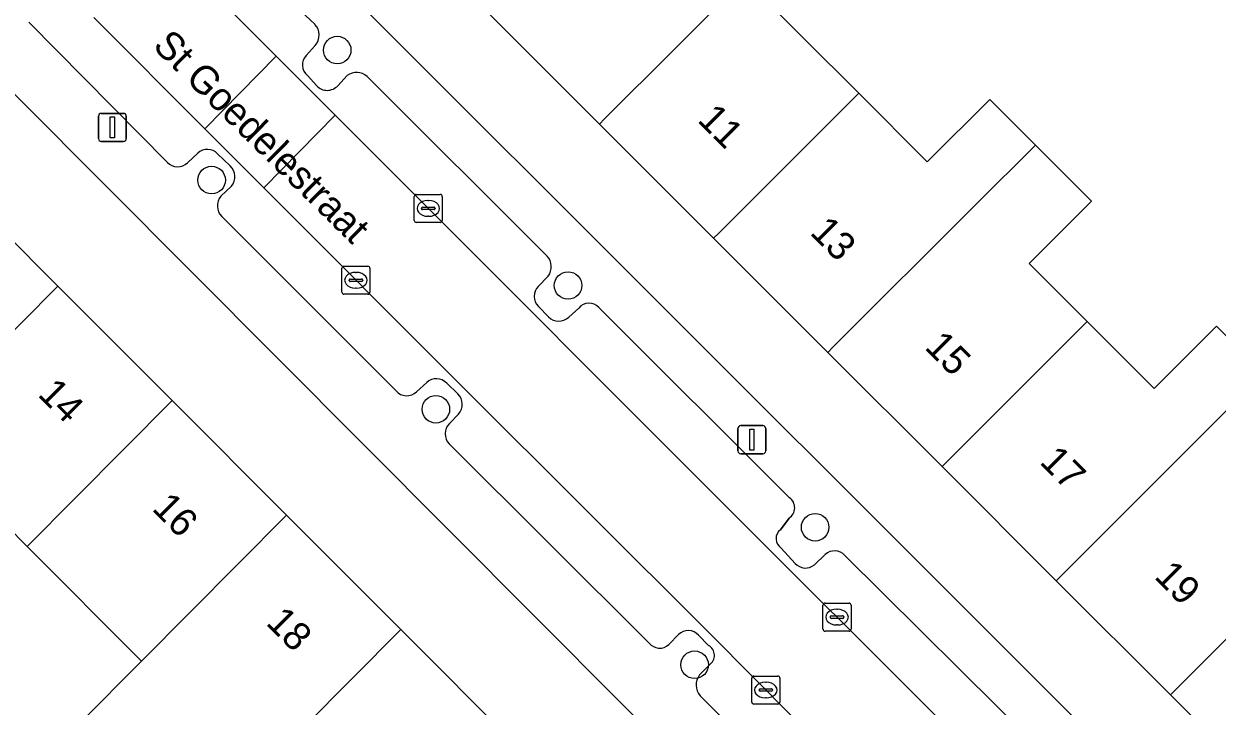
# Model space of a CAD drawing. Extents: x 162523 to 163266, y 381230 to 382050.
# Drawn here: x 162879.64 to 162922.11, y 381652.26 to 381676.55 of the extents above; entities that cross this region are included whole.
import ezdxf

# ---------------------------------------------------------------- set-up
doc = ezdxf.new("R2010")
doc.units = 0
for name, color, linetype in [('IMGEO_Boom', 7, 'Continuous'), ('IMGEO_Erf', 7, 'Continuous'), ('IMGEO_Kolk', 7, 'Continuous'), ('IMGEO_Lichtmast', 7, 'Continuous'), ('IMGEO_Openbare_ruimte_label', 7, 'Continuous'), ('IMGEO_Pand', 7, 'Continuous'), ('IMGEO_Pand_nummerreeks', 7, 'Continuous'), ('IMGEO_Parkeervlak_open', 7, 'Continuous'), ('IMGEO_Rijbaan_lokaal_open', 7, 'Continuous'), ('IMGEO_Voetpad_open', 7, 'Continuous')]:
    doc.layers.add(name, color=color, linetype=linetype)

msp = doc.modelspace()

# ---------------------------------------------------------------- linework, layer by layer
at = {"layer": 'IMGEO_Boom'}
for centre in [(162890.791, 381675.616), (162886.32, 381670.989), (162899.006, 381667.232), (162894.302, 381662.825), (162907.8, 381658.624), (162903.512, 381653.732)]:
    msp.add_circle(centre, 0.489, dxfattribs=at)
at = {"layer": 'IMGEO_Erf'}
for points in [[(162881.716, 381687.133), (162922.581, 381646.284), (162924.703, 381648.404), (162920.45, 381652.657), (162920.379, 381652.728), (162916.456, 381656.651), (162916.385, 381656.722), (162916.314, 381656.793), (162912.391, 381660.716), (162912.32, 381660.787), (162912.249, 381660.858), (162908.326, 381664.781), (162908.255, 381664.852), (162908.184, 381664.923), (162904.26, 381668.847), (162904.189, 381668.918), (162904.118, 381668.989), (162900.195, 381672.912), (162900.124, 381672.983), (162900.053, 381673.054), (162896.13, 381676.977)], [(162905.385, 381678.046), (162909.353, 381674.077), (162911.792, 381671.638), (162914.014, 381673.858), (162915.64, 381672.232), (162915.711, 381672.161), (162917.64, 381670.232), (162915.418, 381668.012), (162917.484, 381665.947), (162919.867, 381663.564), (162920.263, 381663.959), (162922.089, 381665.783), (162923.771, 381664.101)], [(162876.85, 381671.218), (162880.849, 381667.213), (162884.919, 381663.137), (162888.988, 381659.061), (162893.058, 381654.985), (162897.128, 381650.909), (162901.196, 381646.834), (162905.267, 381642.757), (162909.336, 381638.682), (162911.284, 381640.643), (162915.574, 381636.334), (162916.21, 381636.979), (162879.464, 381673.885)], [(162881.631, 381651.654), (162883.818, 381653.856), (162879.758, 381657.941), (162877.555, 381660.157)]]:
    msp.add_lwpolyline(points, dxfattribs=at)
at = {"layer": 'IMGEO_Kolk'}
for p, q in [((162893.605, 381670.477), (162894.457, 381670.477)), ((162893.53, 381669.551), (162893.53, 381670.403)), ((162893.832, 381670.02), (162894.23, 381670.02)), ((162894.018, 381670.257), (162894.043, 381670.257)), ((162894.531, 381670.403), (162894.531, 381669.551)), ((162893.789, 381669.971), (162893.789, 381669.983)), ((162894.227, 381669.934), (162893.829, 381669.934)), ((162894.041, 381669.697), (162894.016, 381669.697)), ((162894.273, 381669.983), (162894.273, 381669.971)), ((162894.457, 381669.477), (162893.605, 381669.477)), ((162891.03, 381667.921), (162891.882, 381667.921)), ((162890.955, 381666.995), (162890.955, 381667.847)), ((162891.257, 381667.464), (162891.655, 381667.464)), ((162891.443, 381667.701), (162891.468, 381667.701)), ((162891.956, 381667.847), (162891.956, 381666.995)), ((162891.214, 381667.415), (162891.214, 381667.427)), ((162891.652, 381667.378), (162891.254, 381667.378)), ((162891.466, 381667.141), (162891.441, 381667.141)), ((162891.698, 381667.427), (162891.698, 381667.415)), ((162891.882, 381666.921), (162891.03, 381666.921)), ((162908.081, 381655), (162908.081, 381655.852)), ((162908.156, 381655.926), (162909.008, 381655.926)), ((162908.569, 381655.706), (162908.594, 381655.706)), ((162909.082, 381655.852), (162909.082, 381655)), ((162908.34, 381655.42), (162908.34, 381655.432)), ((162908.778, 381655.383), (162908.38, 381655.383)), ((162908.383, 381655.469), (162908.781, 381655.469)), ((162908.592, 381655.146), (162908.567, 381655.146)), ((162908.824, 381655.432), (162908.824, 381655.42)), ((162909.008, 381654.926), (162908.156, 381654.926)), ((162905.545, 381652.404), (162905.545, 381653.256)), ((162905.62, 381653.33), (162906.472, 381653.33)), ((162906.033, 381653.11), (162906.058, 381653.11)), ((162906.546, 381653.256), (162906.546, 381652.404)), ((162905.804, 381652.824), (162905.804, 381652.836)), ((162906.242, 381652.787), (162905.844, 381652.787)), ((162905.847, 381652.873), (162906.245, 381652.873)), ((162906.288, 381652.836), (162906.288, 381652.824)), ((162906.472, 381652.33), (162905.62, 381652.33)), ((162906.056, 381652.55), (162906.031, 381652.55))]:
    msp.add_line(p, q, dxfattribs=at)
for points in [[(162893.605, 381670.477), (162894.457, 381670.477)], [(162893.53, 381669.551), (162893.53, 381670.403)], [(162894.531, 381670.403), (162894.531, 381669.551)], [(162894.457, 381669.477), (162893.605, 381669.477)], [(162891.03, 381667.921), (162891.882, 381667.921)], [(162890.955, 381666.995), (162890.955, 381667.847)], [(162891.956, 381667.847), (162891.956, 381666.995)], [(162891.882, 381666.921), (162891.03, 381666.921)], [(162908.081, 381655), (162908.081, 381655.852)], [(162908.156, 381655.926), (162909.008, 381655.926)], [(162909.082, 381655.852), (162909.082, 381655)], [(162909.008, 381654.926), (162908.156, 381654.926)], [(162905.545, 381652.404), (162905.545, 381653.256)], [(162905.62, 381653.33), (162906.472, 381653.33)], [(162906.546, 381653.256), (162906.546, 381652.404)], [(162906.472, 381652.33), (162905.62, 381652.33)]]:
    msp.add_lwpolyline(points, dxfattribs=at)
for centre, radius, start, end in [((162893.607, 381670.401), 0.0765, 91.552, 178.448), ((162893.607, 381670.401), 0.0765, 91.552, 178.448), ((162894.455, 381670.401), 0.0765, 1.552, 88.448), ((162894.455, 381670.401), 0.0765, 1.552, 88.448), ((162893.829, 381669.98), 0.0403, 85.8775, 175.7526), ((162894.234, 381669.982), 0.0386, 1.7309, 96.639), ((162893.826, 381669.97), 0.0366, 178.938, 274.7102), ((162894.23, 381669.977), 0.043, 264.8664, 352.4533), ((162893.607, 381669.553), 0.0765, 181.552, 268.448), ((162893.607, 381669.553), 0.0765, 181.552, 268.448), ((162894.455, 381669.553), 0.0765, 271.552, 358.448), ((162894.455, 381669.553), 0.0765, 271.552, 358.448), ((162891.032, 381667.845), 0.0765, 91.552, 178.448), ((162891.032, 381667.845), 0.0765, 91.552, 178.448), ((162891.88, 381667.845), 0.0765, 1.552, 88.448), ((162891.88, 381667.845), 0.0765, 1.552, 88.448), ((162891.254, 381667.424), 0.0403, 85.8775, 175.7526), ((162891.659, 381667.426), 0.0386, 1.7309, 96.639), ((162891.251, 381667.414), 0.0366, 178.938, 274.7102), ((162891.655, 381667.421), 0.043, 264.8664, 352.4533), ((162891.032, 381666.997), 0.0765, 181.552, 268.448), ((162891.032, 381666.997), 0.0765, 181.552, 268.448), ((162891.88, 381666.997), 0.0765, 271.552, 358.448), ((162891.88, 381666.997), 0.0765, 271.552, 358.448), ((162908.158, 381655.85), 0.0765, 91.552, 178.448), ((162908.158, 381655.85), 0.0765, 91.552, 178.448), ((162909.006, 381655.85), 0.0765, 1.552, 88.448), ((162909.006, 381655.85), 0.0765, 1.552, 88.448), ((162908.38, 381655.429), 0.0403, 85.8775, 175.7526), ((162908.377, 381655.419), 0.0366, 178.938, 274.7102), ((162908.781, 381655.426), 0.043, 264.8664, 352.4533), ((162908.785, 381655.431), 0.0386, 1.7309, 96.639), ((162908.158, 381655.002), 0.0765, 181.552, 268.448), ((162908.158, 381655.002), 0.0765, 181.552, 268.448), ((162909.006, 381655.002), 0.0765, 271.552, 358.448), ((162909.006, 381655.002), 0.0765, 271.552, 358.448), ((162905.622, 381653.254), 0.0765, 91.552, 178.448), ((162905.622, 381653.254), 0.0765, 91.552, 178.448), ((162906.47, 381653.254), 0.0765, 1.552, 88.448), ((162906.47, 381653.254), 0.0765, 1.552, 88.448), ((162905.844, 381652.833), 0.0403, 85.8775, 175.7526), ((162905.841, 381652.823), 0.0366, 178.938, 274.7102), ((162906.245, 381652.83), 0.043, 264.8664, 352.4533), ((162906.249, 381652.835), 0.0386, 1.7309, 96.639), ((162905.622, 381652.406), 0.0765, 181.552, 268.448), ((162905.622, 381652.406), 0.0765, 181.552, 268.448), ((162906.47, 381652.406), 0.0765, 271.552, 358.448), ((162906.47, 381652.406), 0.0765, 271.552, 358.448)]:
    msp.add_arc(centre, radius, start, end, dxfattribs=at)
for centre, major_axis, ratio, start_param, end_param in [((162894.017, 381669.977), (-0.387, 0.002), 0.722429, 4.712389, 7.853982), ((162894.042, 381669.977), (-0.39, 0.002), 0.717154, 1.570796, 4.712389), ((162891.442, 381667.421), (-0.387, 0.002), 0.722429, 4.712389, 7.853982), ((162891.467, 381667.421), (-0.39, 0.002), 0.717154, 1.570796, 4.712389), ((162908.568, 381655.426), (-0.387, 0.002), 0.722429, 4.712389, 7.853982), ((162908.593, 381655.426), (-0.39, 0.002), 0.717154, 1.570796, 4.712389), ((162906.032, 381652.83), (-0.387, 0.002), 0.722429, 4.712389, 7.853982), ((162906.057, 381652.83), (-0.39, 0.002), 0.717154, 1.570796, 4.712389)]:
    msp.add_ellipse(centre, major_axis=major_axis, ratio=ratio, start_param=start_param, end_param=end_param, dxfattribs=at)
at = {"layer": 'IMGEO_Lichtmast'}
for p, q in [((162882.292, 381672.462), (162882.292, 381673.262)), ((162882.292, 381673.262), (162882.292, 381672.462)), ((162882.392, 381673.362), (162883.182, 381673.362)), ((162883.182, 381673.362), (162882.392, 381673.362)), ((162883.282, 381673.262), (162883.282, 381672.462)), ((162883.282, 381672.462), (162883.282, 381673.262)), ((162883.182, 381672.362), (162882.392, 381672.362)), ((162882.392, 381672.362), (162883.182, 381672.362)), ((162905.053, 381661.343), (162905.053, 381662.143)), ((162905.053, 381662.143), (162905.053, 381661.343)), ((162905.153, 381662.243), (162905.943, 381662.243)), ((162905.943, 381662.243), (162905.153, 381662.243)), ((162906.043, 381662.143), (162906.043, 381661.343)), ((162906.043, 381661.343), (162906.043, 381662.143)), ((162905.943, 381661.243), (162905.153, 381661.243)), ((162905.153, 381661.243), (162905.943, 381661.243))]:
    msp.add_line(p, q, dxfattribs=at)
for points in [[(162882.712, 381673.237), (162882.862, 381673.237), (162882.862, 381672.487), (162882.712, 381672.487), (162882.712, 381673.237)], [(162905.473, 381662.118), (162905.623, 381662.118), (162905.623, 381661.368), (162905.473, 381661.368), (162905.473, 381662.118)]]:
    msp.add_lwpolyline(points, dxfattribs=at)
for centre, start, end in [((162882.392, 381673.262), 90, 180), ((162882.392, 381673.262), 90, 180), ((162883.182, 381673.262), 0, 90), ((162883.182, 381673.262), 360, 90), ((162882.392, 381672.462), 180, 270), ((162882.392, 381672.462), 180, 270), ((162883.182, 381672.462), 270, 0), ((162883.182, 381672.462), 270, 0), ((162905.153, 381662.143), 90, 180), ((162905.153, 381662.143), 90, 180), ((162905.943, 381662.143), 0, 90), ((162905.943, 381662.143), 360, 90), ((162905.153, 381661.343), 180, 270), ((162905.153, 381661.343), 180, 270), ((162905.943, 381661.343), 270, 0), ((162905.943, 381661.343), 270, 0)]:
    msp.add_arc(centre, 0.1, start, end, dxfattribs=at)
at = {"layer": 'IMGEO_Pand'}
for points in [[(162907.509, 381680.362), (162905.804, 381682.067), (162904.148, 381680.413), (162903.582, 381679.848), (162901.222, 381682.207), (162896.245, 381677.234), (162896.059, 381677.048), (162896.13, 381676.977), (162900.053, 381673.054), (162900.124, 381672.983), (162900.309, 381673.167), (162905.288, 381678.143), (162905.375, 381678.23)], [(162905.385, 381678.046), (162905.288, 381678.143), (162900.309, 381673.167), (162900.124, 381672.983), (162900.195, 381672.912), (162904.118, 381668.989), (162904.189, 381668.918), (162904.372, 381669.1), (162909.353, 381674.077)], [(162908.255, 381664.852), (162908.436, 381665.033), (162913.502, 381670.096), (162915.64, 381672.232), (162914.014, 381673.858), (162911.792, 381671.638), (162909.353, 381674.077), (162904.372, 381669.1), (162904.189, 381668.918), (162904.26, 381668.847), (162908.184, 381664.923)], [(162912.32, 381660.787), (162912.499, 381660.966), (162917.484, 381665.947), (162915.418, 381668.012), (162917.64, 381670.232), (162915.711, 381672.161), (162915.64, 381672.232), (162913.502, 381670.096), (162908.436, 381665.033), (162908.255, 381664.852), (162908.326, 381664.781), (162912.249, 381660.858)], [(162880.849, 381667.213), (162876.85, 381671.218), (162873.391, 381667.608), (162871.8, 381665.947), (162873.922, 381663.812), (162871.713, 381661.587), (162873.491, 381659.806), (162875.617, 381661.946)], [(162880.849, 381667.213), (162875.617, 381661.946), (162873.491, 381659.806), (162875.354, 381657.94), (162877.555, 381660.157), (162879.758, 381657.941), (162884.919, 381663.137)], [(162916.385, 381656.722), (162916.563, 381656.899), (162921.63, 381661.962), (162923.771, 381664.101), (162922.089, 381665.783), (162920.263, 381663.959), (162919.867, 381663.564), (162917.484, 381665.947), (162912.499, 381660.966), (162912.32, 381660.787), (162912.391, 381660.716), (162916.314, 381656.793)], [(162920.45, 381652.657), (162920.626, 381652.832), (162925.615, 381657.817), (162923.492, 381659.939), (162924.578, 381661.024), (162925.713, 381662.158), (162923.771, 381664.101), (162921.63, 381661.962), (162916.563, 381656.899), (162916.385, 381656.722), (162916.456, 381656.651), (162920.379, 381652.728)], [(162888.988, 381659.061), (162884.919, 381663.137), (162879.758, 381657.941), (162883.818, 381653.856)], [(162920.45, 381652.657), (162924.703, 381648.404), (162926.264, 381649.964), (162928.24, 381651.939), (162929.867, 381653.565), (162927.602, 381655.829), (162928.796, 381657.022), (162929.823, 381658.048), (162927.836, 381660.036), (162925.615, 381657.817), (162920.626, 381652.832)], [(162888.988, 381659.061), (162883.818, 381653.856), (162881.631, 381651.654), (162883.58, 381649.702), (162885.762, 381651.9), (162887.879, 381649.771), (162893.058, 381654.985)], [(162897.128, 381650.909), (162893.058, 381654.985), (162887.879, 381649.771), (162885.7, 381647.578), (162888.109, 381645.166), (162889.771, 381643.502), (162891.964, 381645.71)]]:
    msp.add_lwpolyline(points, close=True, dxfattribs=at)
at = {"layer": 'IMGEO_Parkeervlak_open'}
for points in [[(162889.998, 381676.532), (162888.178, 381678.232), (162886.111, 381680.44), (162884.081, 381682.674), (162882.728, 381684.187)], [(162887.014, 381676.996), (162888.615, 381675.394), (162890.715, 381673.293), (162906.585, 381657.416), (162914.043, 381649.979), (162915.358, 381648.667), (162916.129, 381647.892), (162921.134, 381642.861), (162921.894, 381642.081)], [(162879.809, 381676.605), (162884.745, 381671.613)], [(162919.687, 381639.115), (162913.528, 381645.291), (162912.703, 381646.119), (162911.448, 381647.385), (162904.104, 381654.791), (162895.257, 381663.613), (162888.18, 381670.707), (162886.082, 381672.809), (162882.128, 381676.772)], [(162889.683, 381675.42), (162890.01, 381675.782)], [(162890.064, 381674.346), (162889.734, 381674.713)], [(162891.15, 381674.709), (162890.808, 381674.348)], [(162898.26, 381668.283), (162891.852, 381674.677)], [(162885.461, 381671.602), (162885.824, 381671.944)], [(162886.533, 381671.922), (162886.978, 381671.488)], [(162887.025, 381670.771), (162886.65, 381670.412)], [(162886.682, 381669.69), (162892.887, 381663.478)], [(162897.946, 381667.2), (162898.302, 381667.566)], [(162898.311, 381666.116), (162897.949, 381666.489)], [(162899.386, 381666.432), (162899.032, 381666.106)], [(162906.894, 381659.676), (162900.1, 381666.45)], [(162893.612, 381663.447), (162893.975, 381663.783)], [(162894.686, 381663.753), (162895.088, 381663.376)], [(162895.103, 381662.657), (162894.785, 381662.323)], [(162894.771, 381661.591), (162901.89, 381654.499)], [(162906.574, 381658.539), (162906.874, 381658.952)], [(162907.086, 381657.339), (162906.593, 381657.886)], [(162908.154, 381657.661), (162907.775, 381657.291)], [(162915.653, 381650.878), (162908.86, 381657.625)], [(162902.594, 381654.449), (162902.941, 381654.81)], [(162903.651, 381654.779), (162904.011, 381654.418)], [(162904.038, 381653.726), (162903.689, 381653.368)], [(162903.71, 381652.623), (162910.496, 381645.822)]]:
    msp.add_lwpolyline(points, dxfattribs=at)
for centre, radius, start, end in [((162889.584, 381676.15), 0.563, 319.1708, 42.6625), ((162890.023, 381675.089), 0.475, 135.8242, 232.4276), ((162891.482, 381674.28), 0.543, 47.0295, 127.7505), ((162890.435, 381674.681), 0.5, 222.0579, 318.2501), ((162886.168, 381671.582), 0.499, 42.9034, 133.542), ((162885.108, 381671.965), 0.506, 224.0632, 314.1765), ((162886.636, 381671.106), 0.513, 319.2978, 48.2031), ((162887.061, 381670.069), 0.536, 140.1465, 224.929), ((162897.839, 381667.899), 0.57, 324.3376, 42.3672), ((162898.295, 381666.846), 0.497, 134.625, 225.8585), ((162899.751, 381666.137), 0.469, 41.8339, 141.0544), ((162898.677, 381666.483), 0.518, 225.1083, 313.3025), ((162894.315, 381663.405), 0.509, 43.2006, 131.9671), ((162893.265, 381663.82), 0.51, 222.1882, 312.915), ((162894.724, 381663.009), 0.517, 317.1232, 45.2671), ((162895.16, 381661.95), 0.529, 135.1387, 222.67), ((162906.632, 381659.321), 0.441, 303.2811, 53.5542), ((162906.802, 381658.219), 0.393, 125.4181, 237.9152), ((162908.488, 381657.272), 0.513, 43.5368, 130.6251), ((162907.455, 381657.669), 0.495, 221.7876, 310.2421), ((162903.281, 381654.458), 0.49, 41.0013, 133.9986), ((162902.266, 381654.809), 0.487, 219.4957, 312.3794), ((162903.81, 381654.064), 0.407, 304.05, 60.4188), ((162904.152, 381653.008), 0.587, 142.1824, 221.0469)]:
    msp.add_arc(centre, radius, start, end, dxfattribs=at)
at = {"layer": 'IMGEO_Rijbaan_lokaal_open'}
msp.add_lwpolyline([(162882.128, 381676.772), (162886.082, 381672.809), (162888.615, 381675.394), (162887.014, 381676.996)], dxfattribs=at)
for points in [[(162890.715, 381673.293), (162888.615, 381675.394), (162886.082, 381672.809), (162888.18, 381670.707)], [(162914.043, 381649.979), (162906.585, 381657.416), (162890.715, 381673.293), (162888.18, 381670.707), (162895.257, 381663.613), (162904.104, 381654.791), (162911.448, 381647.385)]]:
    msp.add_lwpolyline(points, close=True, dxfattribs=at)
at = {"layer": 'IMGEO_Voetpad_open'}
for points in [[(162862.821, 381717.136), (162859.084, 381716.26), (162859.316, 381715.205), (162862.283, 381703.406), (162863.706, 381697.45), (162864.542, 381694.268), (162878.048, 381675.26), (162879.384, 381673.963), (162879.464, 381673.885), (162916.21, 381636.979), (162915.574, 381636.334), (162916.591, 381635.339), (162921.065, 381631.586), (162928.147, 381625.792), (162934.732, 381620.307), (162938.568, 381617.099), (162941.732, 381621.049), (162938.502, 381623.781)], [(162943.398, 381624.302), (162943.706, 381624.046), (162944.009, 381623.798), (162945.701, 381625.847), (162927.728, 381640.815), (162930.014, 381643.539), (162947.985, 381628.574), (162949.739, 381630.435), (162945.856, 381633.664), (162939.283, 381639.132), (162927.706, 381648.764), (162926.264, 381649.964), (162924.703, 381648.404), (162922.581, 381646.284), (162881.716, 381687.133), (162883.851, 381689.256), (162885.269, 381690.666), (162884.235, 381691.7), (162882.007, 381693.926), (162879.774, 381696.157)], [(162882.728, 381684.187), (162884.081, 381682.674), (162886.111, 381680.44), (162888.178, 381678.232), (162889.998, 381676.532)], [(162884.745, 381671.613), (162879.809, 381676.605)], [(162890.01, 381675.782), (162889.683, 381675.42)], [(162889.734, 381674.713), (162890.064, 381674.346)], [(162890.808, 381674.348), (162891.15, 381674.709)], [(162891.852, 381674.677), (162898.26, 381668.283)], [(162885.824, 381671.944), (162885.461, 381671.602)], [(162886.978, 381671.488), (162886.533, 381671.922)], [(162886.65, 381670.412), (162887.025, 381670.771)], [(162892.887, 381663.478), (162886.682, 381669.69)], [(162898.302, 381667.566), (162897.946, 381667.2)], [(162897.949, 381666.489), (162898.311, 381666.116)], [(162899.032, 381666.106), (162899.386, 381666.432)], [(162900.1, 381666.45), (162906.894, 381659.676)], [(162893.975, 381663.783), (162893.612, 381663.447)], [(162895.088, 381663.376), (162894.686, 381663.753)], [(162894.785, 381662.323), (162895.103, 381662.657)], [(162901.89, 381654.499), (162894.771, 381661.591)], [(162906.874, 381658.952), (162906.574, 381658.539)], [(162906.593, 381657.886), (162907.086, 381657.339)], [(162907.775, 381657.291), (162908.154, 381657.661)], [(162908.86, 381657.625), (162915.653, 381650.878)], [(162902.941, 381654.81), (162902.594, 381654.449)], [(162904.011, 381654.418), (162903.651, 381654.779)], [(162903.689, 381653.368), (162904.038, 381653.726)], [(162910.496, 381645.822), (162903.71, 381652.623)]]:
    msp.add_lwpolyline(points, dxfattribs=at)
for centre, radius, start, end in [((162889.584, 381676.15), 0.563, 319.1708, 42.6625), ((162890.023, 381675.089), 0.475, 135.8242, 232.4276), ((162891.482, 381674.28), 0.543, 47.0295, 127.7505), ((162890.435, 381674.681), 0.5, 222.0579, 318.2501), ((162886.168, 381671.582), 0.499, 42.9034, 133.542), ((162885.108, 381671.965), 0.506, 224.0632, 314.1765), ((162886.636, 381671.106), 0.513, 319.2978, 48.2031), ((162887.061, 381670.069), 0.536, 140.1465, 224.929), ((162897.839, 381667.899), 0.57, 324.3376, 42.3672), ((162898.295, 381666.846), 0.497, 134.625, 225.8585), ((162899.751, 381666.137), 0.469, 41.8339, 141.0544), ((162898.677, 381666.483), 0.518, 225.1083, 313.3025), ((162894.315, 381663.405), 0.509, 43.2006, 131.9671), ((162893.265, 381663.82), 0.51, 222.1882, 312.915), ((162894.724, 381663.009), 0.517, 317.1232, 45.2671), ((162895.16, 381661.95), 0.529, 135.1387, 222.67), ((162906.632, 381659.321), 0.441, 303.2811, 53.5542), ((162906.802, 381658.219), 0.393, 125.4181, 237.9152), ((162908.488, 381657.272), 0.513, 43.5368, 130.6251), ((162907.455, 381657.669), 0.495, 221.7876, 310.2421), ((162903.281, 381654.458), 0.49, 41.0013, 133.9986), ((162902.266, 381654.809), 0.487, 219.4957, 312.3794), ((162903.81, 381654.064), 0.407, 304.05, 60.4188), ((162904.152, 381653.008), 0.587, 142.1824, 221.0469)]:
    msp.add_arc(centre, radius, start, end, dxfattribs=at)

# ---------------------------------------------------------------- texts
at = {"layer": 'IMGEO_Openbare_ruimte_label'}
msp.add_text('St Goedelestraat', height=1, rotation=315.4052, dxfattribs=at).set_placement((162884.186, 381675.717))
at = {"layer": 'IMGEO_Pand_nummerreeks'}
for s, rotation, p in [('11', 314.9999, (162903.576, 381673.094)), ('13', 315, (162907.582, 381669.09)), ('15', 315, (162911.667, 381665.005)), ('14', 314.9559, (162880.098, 381663.323)), ('17', 315, (162915.753, 381660.92)), ('16', 314.9559, (162884.157, 381659.258)), ('19', 315, (162919.838, 381656.834)), ('18', 314.9559, (162888.218, 381655.191))]:
    msp.add_text(s, height=1, rotation=rotation, dxfattribs=at).set_placement(p)

doc.saveas('drawing.dxf')
